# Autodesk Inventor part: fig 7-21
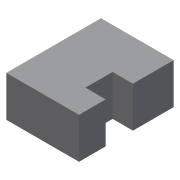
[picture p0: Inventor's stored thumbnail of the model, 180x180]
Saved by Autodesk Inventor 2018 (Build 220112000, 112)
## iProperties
Created: 2010-03
Part Number: fig 7-21
Document SubType Name: Modeling
Designer: CADSoft
Density: 1 g/cm^3
Material: Generic
Appearance: Default
Author: CADSoft
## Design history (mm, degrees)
sketch "Sketch1"
  geometry: L1 (-16.027, 20.205)-(19.726, 20.205); L2 (19.726, 20.205)-(19.726, -26.37); L3 (19.726, -26.37)-(-16.027, -26.37); L4 (-16.027, -26.37)-(-16.027, 20.205); 1 further point
  constraints: 8 end point, 2 parallel, 1 horizontal, 1 perpendicular
extrude "Extrusion1" new body sketch "Sketch1" distance "d0" = 20; taper "d1" = 0 deg
sketch "Sketch2"
  geometry: L1 (-20, 46.575)-(-20, 0) reference; L2 (0, 46.575)-(0, 0) reference; L3 (-20, 13.159)-(0, 13.159); L4 (0, 13.159)-(0, 33.527); L5 (0, 33.527)-(-20, 33.527); L6 (-20, 33.527)-(-20, 13.159); 1 further point
  constraints: 8 end point, 2 parallel, 2 point on line, 1 horizontal, 1 perpendicular
extrude "Extrusion2" cut sketch "Sketch2" distance "d2" = 10; taper "d3" = 0 deg
node "Direct Edit2"
body "Solid1"
move_body "Move2" dims "d9" = 7
other parameters: "d7" = 0, "d8" = 0
